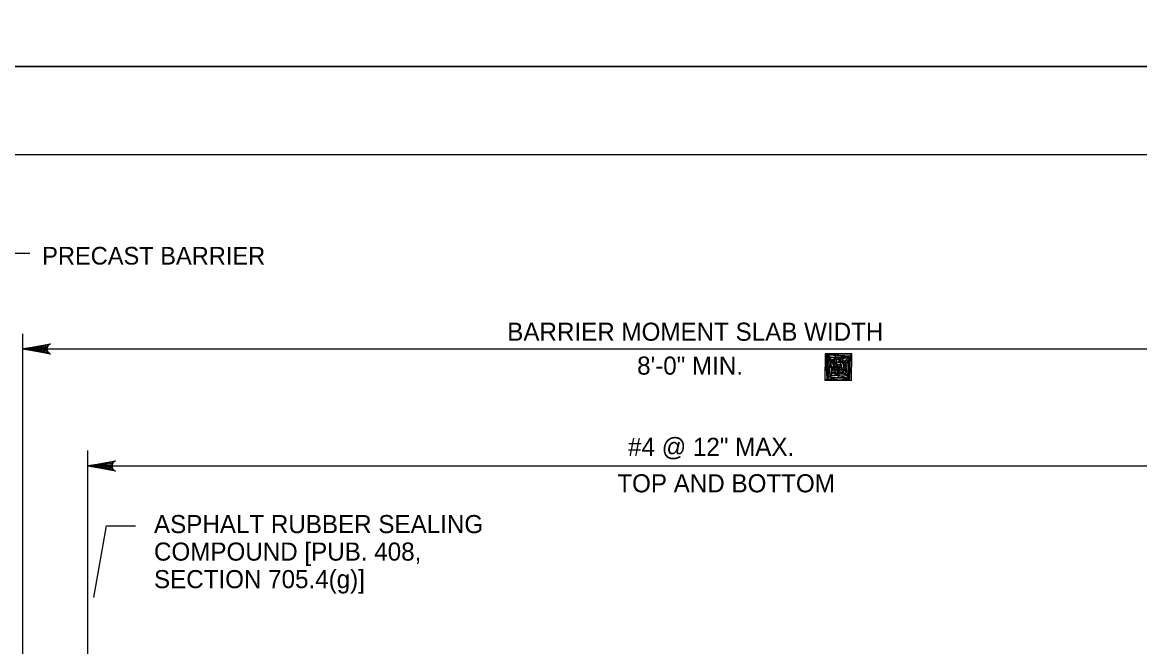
# Model space of a CAD drawing. Extents: x 638167 to 640248, y 296544 to 298920.
# Drawn here: x 638721.8 to 638911.6, y 297633.9 to 297740 of the extents above; entities that cross this region are included whole.
import ezdxf

# ---------------------------------------------------------------- set-up
doc = ezdxf.new("R2010")
doc.units = 0
doc.layers.add('1', color=7, linetype='Continuous')
doc.layers.add('PLT-BNDY', color=7, linetype='Continuous')

msp = doc.modelspace()

# ---------------------------------------------------------------- linework, layer by layer
at = {"layer": '1'}
for p, q in [((638991.78, 297717.48), (638205.78, 297717.48)), ((638723.06, 297700.72), (638716.89, 297700.72)), ((638721.84, 297605.57), (638721.84, 297687.07)), ((638721.84, 297684.5), (638965.68, 297684.5)), ((638860.45, 297681.4), (638860.45, 297681.4)), ((638732.89, 297601.48), (638732.89, 297667.24)), ((638732.89, 297664.62), (638973.66, 297664.62)), ((638733.89, 297642.3), (638736.09, 297654.45)), ((638736.09, 297654.45), (638741.02, 297654.45))]:
    msp.add_line(p, q, dxfattribs=at)
for points in [[(638721.84, 297684.5), (638726.54, 297685.38), (638726.36, 297685.26), (638726.18, 297685.13), (638726.09, 297684.97), (638725.99, 297684.82), (638725.97, 297684.66), (638725.94, 297684.5), (638725.97, 297684.34), (638725.99, 297684.19), (638726.09, 297684.03), (638726.18, 297683.87), (638726.36, 297683.75), (638726.54, 297683.62), (638721.84, 297684.5), (638726.36, 297683.75), (638726.18, 297683.87), (638721.84, 297684.5), (638726.09, 297684.03), (638725.99, 297684.19), (638721.84, 297684.5), (638725.97, 297684.34), (638725.94, 297684.5), (638721.84, 297684.5), (638725.97, 297684.66), (638725.99, 297684.82), (638721.84, 297684.5), (638726.09, 297684.97), (638726.18, 297685.13), (638721.84, 297684.5), (638726.36, 297685.26)], [(638858.21, 297683.69), (638858.16, 297679.17), (638862.69, 297679.12), (638862.73, 297683.64), (638858.21, 297683.69), (638858.46, 297679.45), (638862.41, 297679.29), (638862.51, 297683.42), (638858.54, 297683.37), (638858.71, 297679.76), (638862.17, 297679.6), (638862.26, 297683.05), (638858.78, 297683.06), (638858.99, 297680.03), (638861.95, 297679.94), (638861.95, 297682.81), (638859.12, 297682.65), (638859.34, 297680.31), (638861.62, 297680.22), (638861.64, 297682.5), (638859.42, 297682.34), (638859.65, 297680.67), (638861.28, 297680.5), (638861.39, 297682.14), (638859.67, 297682.22), (638859.81, 297680.95), (638861.04, 297680.88), (638861.05, 297681.74), (638860.19, 297681.93), (638860.12, 297681.19), (638860.73, 297681.13), (638860.8, 297681.49), (638860.49, 297681.5), (638858.42, 297683.55), (638862.61, 297683.45), (638858.31, 297679.24), (638862.35, 297679.47), (638858.48, 297683.37), (638862.25, 297682), (638858.59, 297682.69), (638862.15, 297680.68), (638858.55, 297681.61), (638862.05, 297680.03), (638858.72, 297680.62), (638861.8, 297679.6), (638859.17, 297679.6), (638859.95, 297683.29), (638860.47, 297679.65), (638860.94, 297683.22), (638862.13, 297679.51), (638862.45, 297683.23), (638861.09, 297680.2), (638858.35, 297683.43), (638858.65, 297679.51), (638859.27, 297682.68), (638862.2, 297683.17), (638858.91, 297683.43)], [(638732.89, 297664.62), (638737.59, 297665.5), (638737.41, 297665.37), (638737.23, 297665.25), (638737.14, 297665.09), (638737.04, 297664.93), (638737.02, 297664.78), (638736.99, 297664.62), (638737.02, 297664.46), (638737.04, 297664.3), (638737.14, 297664.15), (638737.23, 297663.99), (638737.41, 297663.86), (638737.59, 297663.74), (638732.89, 297664.62), (638737.41, 297663.86), (638737.23, 297663.99), (638732.89, 297664.62), (638737.14, 297664.15), (638737.04, 297664.3), (638732.89, 297664.62), (638737.02, 297664.46), (638736.99, 297664.62), (638732.89, 297664.62), (638737.02, 297664.78), (638737.04, 297664.93), (638732.89, 297664.62), (638737.14, 297665.09), (638737.23, 297665.25), (638732.89, 297664.62), (638737.41, 297665.37)]]:
    msp.add_lwpolyline(points, dxfattribs=at)
at = {"layer": 'PLT-BNDY'}
for points in [[(638166.78, 298326.48), (639007.78, 298326.48), (639007.78, 297732.48), (638166.78, 297732.48)], [(638166.78, 297732.48), (639007.78, 297732.48), (639007.78, 297138.48), (638166.78, 297138.48)]]:
    msp.add_lwpolyline(points, close=True, dxfattribs=at)

# ---------------------------------------------------------------- texts
at = {"layer": '1'}
for s, height, p in [('PRECAST BARRIER', 3, (638725.14, 297698.83)), ('BARRIER MOMENT SLAB WIDTH', 3.072, (638804.17, 297685.89)), ('8\'-0" MIN.', 3.072, (638826.24, 297680.13)), ('#4 @ 12" MAX.', 3.072, (638824.7, 297666.34)), ('TOP AND BOTTOM', 3.072, (638822.87, 297660.14)), ('ASPHALT RUBBER SEALING', 3.072, (638744.14, 297653.21)), ('COMPOUND [PUB. 408,', 3.072, (638744.14, 297648.54)), ('SECTION 705.4(g)]', 3.072, (638744.14, 297643.86))]:
    msp.add_text(s, height=height, dxfattribs=at).set_placement(p)

doc.saveas('drawing.dxf')
